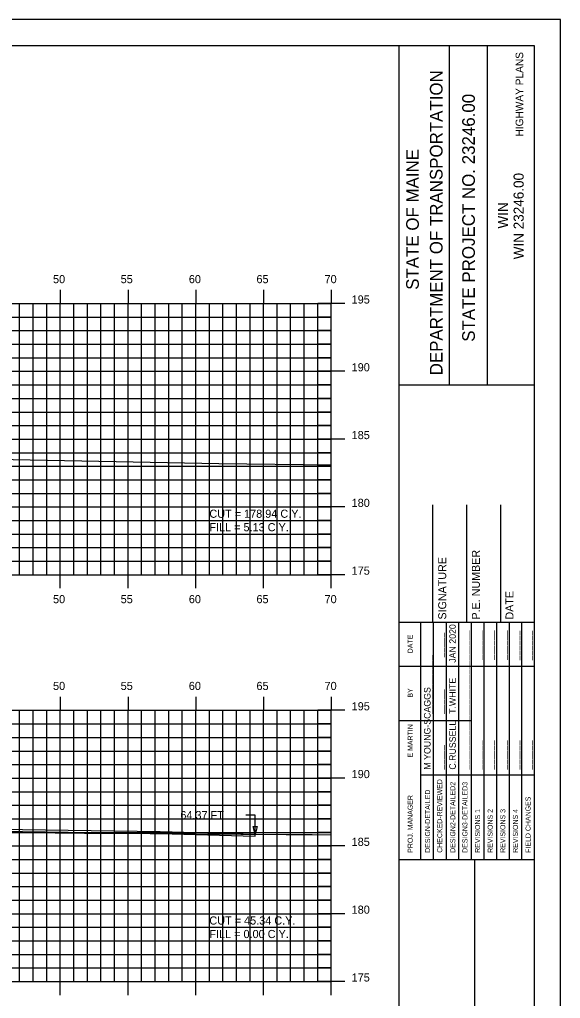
# Model space of a CAD drawing. Extents: x 1139650 to 1139820, y 608981 to 609091.
# Drawn here: x 1139780.2 to 1139820.1, y 609019.1 to 609091.3 of the extents above; entities that cross this region are included whole.
import ezdxf

# ---------------------------------------------------------------- set-up
doc = ezdxf.new("R2010")
doc.units = 0
for name, color, linetype in [('BORDER', 7, 'Continuous'), ('D_Roadway_Edge_Shoulder', 7, 'Continuous'), ('D_Text_Standard', 7, 'Continuous'), ('H_V ANNOTATION', 7, 'Continuous'), ('HIGHWAY_TITLE', 7, 'Continuous'), ('MAJOR', 7, 'Continuous'), ('MINOR', 7, 'Continuous'), ('PLOT BOUNDARY', 7, 'Continuous'), ('S_Roadway_Centerline', 7, 'Continuous')]:
    doc.layers.add(name, color=color, linetype=linetype)

msp = doc.modelspace()

# ---------------------------------------------------------------- linework, layer by layer
at = {"layer": 'BORDER'}
for p, q in [((1139808.219, 608984.335), (1139808.219, 609089.335)), ((1139811.947, 609064.332), (1139811.947, 609089.332)), ((1139814.742, 609064.332), (1139814.742, 609089.332)), ((1139808.219, 609064.329), (1139818.219, 609064.329)), ((1139810.719, 609046.838), (1139810.719, 609055.485)), ((1139813.219, 609046.838), (1139813.219, 609055.485)), ((1139815.719, 609046.838), (1139815.719, 609055.485)), ((1139808.219, 609046.838), (1139818.219, 609046.838)), ((1139808.219, 609029.338), (1139818.219, 609029.338)), ((1139813.81, 608994.338), (1139813.81, 609029.338))]:
    msp.add_line(p, q, dxfattribs=at)
msp.add_lwpolyline([(1139658.219, 608984.335), (1139818.219, 608984.335), (1139818.219, 609089.335), (1139658.219, 609089.335)], close=True, dxfattribs=at)
for points in [[(1139809.833, 609043.588), (1139809.833, 609046.838)], [(1139810.766, 609029.341), (1139810.766, 609046.838)], [(1139811.698, 609046.838), (1139811.698, 609029.341)], [(1139812.629, 609029.341), (1139812.629, 609046.838)], [(1139813.561, 609029.341), (1139813.561, 609046.838)], [(1139814.493, 609029.341), (1139814.493, 609046.838)], [(1139815.424, 609029.341), (1139815.424, 609046.838)], [(1139816.356, 609029.341), (1139816.356, 609046.838)], [(1139817.288, 609029.341), (1139817.288, 609046.838)], [(1139809.834, 609029.341), (1139809.834, 609046.132)], [(1139808.219, 609043.588), (1139818.219, 609043.588)], [(1139808.219, 609039.588), (1139809.834, 609039.588)], [(1139809.833, 609039.588), (1139813.56, 609039.588)], [(1139809.833, 609035.588), (1139818.219, 609035.588)]]:
    msp.add_lwpolyline(points, dxfattribs=at)
at = {"layer": 'D_Roadway_Edge_Shoulder'}
for points in [[(1139797.588, 609031.189), (1139790.588, 609031.365), (1139748.218, 609031.989)], [(1139748.218, 609031.989), (1139748.218, 609031.864), (1139790.588, 609031.24), (1139797.588, 609031.064), (1139797.588, 609031.189)]]:
    msp.add_lwpolyline(points, dxfattribs=at)
at = {"layer": 'D_Text_Standard'}
msp.add_lwpolyline([(1139797.588, 609031.189), (1139797.592, 609032.608), (1139796.913, 609032.608)], dxfattribs=at)
msp.add_lwpolyline([(1139797.588, 609031.189), (1139797.445, 609031.771), (1139797.736, 609031.77)], close=True, dxfattribs=at)
at = {"layer": 'MAJOR'}
for p, q in [((1139783.218, 609071.337), (1139783.218, 609070.335)), ((1139788.218, 609071.337), (1139788.218, 609070.335)), ((1139793.218, 609071.337), (1139793.218, 609070.335)), ((1139798.218, 609071.337), (1139798.218, 609070.335)), ((1139803.218, 609071.337), (1139803.218, 609070.335)), ((1139663.218, 609070.335), (1139803.218, 609070.335)), ((1139663.218, 609070.335), (1139803.218, 609070.335)), ((1139783.218, 609050.335), (1139783.218, 609070.335)), ((1139788.218, 609050.335), (1139788.218, 609070.335)), ((1139793.218, 609050.335), (1139793.218, 609070.335)), ((1139798.218, 609050.335), (1139798.218, 609070.335)), ((1139804.22, 609070.335), (1139802.216, 609070.335)), ((1139803.218, 609050.335), (1139803.218, 609070.335)), ((1139803.218, 609050.335), (1139803.218, 609070.335)), ((1139663.218, 609065.335), (1139803.218, 609065.335)), ((1139804.22, 609065.335), (1139802.216, 609065.335)), ((1139663.218, 609060.335), (1139803.218, 609060.335)), ((1139804.22, 609060.335), (1139802.216, 609060.335)), ((1139663.218, 609055.335), (1139803.218, 609055.335)), ((1139804.22, 609055.335), (1139802.216, 609055.335)), ((1139663.218, 609050.335), (1139803.218, 609050.335)), ((1139663.218, 609050.335), (1139803.218, 609050.335)), ((1139783.218, 609049.333), (1139783.218, 609050.335)), ((1139788.218, 609049.333), (1139788.218, 609050.335)), ((1139793.218, 609049.333), (1139793.218, 609050.335)), ((1139798.218, 609049.333), (1139798.218, 609050.335)), ((1139804.22, 609050.335), (1139802.216, 609050.335)), ((1139803.218, 609049.333), (1139803.218, 609050.335)), ((1139783.218, 609041.337), (1139783.218, 609040.335)), ((1139788.218, 609041.337), (1139788.218, 609040.335)), ((1139793.218, 609041.337), (1139793.218, 609040.335)), ((1139798.218, 609041.337), (1139798.218, 609040.335)), ((1139803.218, 609041.337), (1139803.218, 609040.335)), ((1139663.218, 609040.335), (1139803.218, 609040.335)), ((1139663.218, 609040.335), (1139803.218, 609040.335)), ((1139783.218, 609020.335), (1139783.218, 609040.335)), ((1139788.218, 609020.335), (1139788.218, 609040.335)), ((1139793.218, 609020.335), (1139793.218, 609040.335)), ((1139798.218, 609020.335), (1139798.218, 609040.335)), ((1139804.22, 609040.335), (1139802.216, 609040.335)), ((1139803.218, 609020.335), (1139803.218, 609040.335)), ((1139803.218, 609020.335), (1139803.218, 609040.335)), ((1139663.218, 609035.335), (1139803.218, 609035.335)), ((1139804.22, 609035.335), (1139802.216, 609035.335)), ((1139663.218, 609030.335), (1139803.218, 609030.335)), ((1139804.22, 609030.335), (1139802.216, 609030.335)), ((1139663.218, 609025.335), (1139803.218, 609025.335)), ((1139804.22, 609025.335), (1139802.216, 609025.335)), ((1139663.218, 609020.335), (1139803.218, 609020.335)), ((1139663.218, 609020.335), (1139803.218, 609020.335)), ((1139783.218, 609019.333), (1139783.218, 609020.335)), ((1139788.218, 609019.333), (1139788.218, 609020.335)), ((1139793.218, 609019.333), (1139793.218, 609020.335)), ((1139798.218, 609019.333), (1139798.218, 609020.335)), ((1139804.22, 609020.335), (1139802.216, 609020.335)), ((1139803.218, 609019.333), (1139803.218, 609020.335))]:
    msp.add_line(p, q, dxfattribs=at)
at = {"layer": 'MINOR'}
for p, q in [((1139780.218, 609050.335), (1139780.218, 609070.335)), ((1139781.218, 609050.335), (1139781.218, 609070.335)), ((1139782.218, 609050.335), (1139782.218, 609070.335)), ((1139784.218, 609050.335), (1139784.218, 609070.335)), ((1139785.218, 609050.335), (1139785.218, 609070.335)), ((1139786.218, 609050.335), (1139786.218, 609070.335)), ((1139787.218, 609050.335), (1139787.218, 609070.335)), ((1139789.218, 609050.335), (1139789.218, 609070.335)), ((1139790.218, 609050.335), (1139790.218, 609070.335)), ((1139791.218, 609050.335), (1139791.218, 609070.335)), ((1139792.218, 609050.335), (1139792.218, 609070.335)), ((1139794.218, 609050.335), (1139794.218, 609070.335)), ((1139795.218, 609050.335), (1139795.218, 609070.335)), ((1139796.218, 609050.335), (1139796.218, 609070.335)), ((1139797.218, 609050.335), (1139797.218, 609070.335)), ((1139799.218, 609050.335), (1139799.218, 609070.335)), ((1139800.218, 609050.335), (1139800.218, 609070.335)), ((1139801.218, 609050.335), (1139801.218, 609070.335)), ((1139802.218, 609050.335), (1139802.218, 609070.335)), ((1139663.218, 609069.335), (1139803.218, 609069.335)), ((1139803.218, 609069.335), (1139802.216, 609069.335)), ((1139663.218, 609068.335), (1139803.218, 609068.335)), ((1139803.218, 609068.335), (1139802.216, 609068.335)), ((1139663.218, 609067.335), (1139803.218, 609067.335)), ((1139803.218, 609067.335), (1139802.216, 609067.335)), ((1139663.218, 609066.335), (1139803.218, 609066.335)), ((1139803.218, 609066.335), (1139802.216, 609066.335)), ((1139663.218, 609064.335), (1139803.218, 609064.335)), ((1139803.218, 609064.335), (1139802.216, 609064.335)), ((1139663.218, 609063.335), (1139803.218, 609063.335)), ((1139803.218, 609063.335), (1139802.216, 609063.335)), ((1139663.218, 609062.335), (1139803.218, 609062.335)), ((1139803.218, 609062.335), (1139802.216, 609062.335)), ((1139663.218, 609061.335), (1139803.218, 609061.335)), ((1139803.218, 609061.335), (1139802.216, 609061.335)), ((1139663.218, 609059.335), (1139803.218, 609059.335)), ((1139803.218, 609059.335), (1139802.216, 609059.335)), ((1139663.218, 609058.335), (1139803.218, 609058.335)), ((1139803.218, 609058.335), (1139802.216, 609058.335)), ((1139663.218, 609057.335), (1139803.218, 609057.335)), ((1139803.218, 609057.335), (1139802.216, 609057.335)), ((1139663.218, 609056.335), (1139803.218, 609056.335)), ((1139803.218, 609056.335), (1139802.216, 609056.335)), ((1139663.218, 609054.335), (1139803.218, 609054.335)), ((1139803.218, 609054.335), (1139802.216, 609054.335)), ((1139663.218, 609053.335), (1139803.218, 609053.335)), ((1139803.218, 609053.335), (1139802.216, 609053.335)), ((1139663.218, 609052.335), (1139803.218, 609052.335)), ((1139803.218, 609052.335), (1139802.216, 609052.335)), ((1139663.218, 609051.335), (1139803.218, 609051.335)), ((1139803.218, 609051.335), (1139802.216, 609051.335)), ((1139780.218, 609020.335), (1139780.218, 609040.335)), ((1139781.218, 609020.335), (1139781.218, 609040.335)), ((1139782.218, 609020.335), (1139782.218, 609040.335)), ((1139784.218, 609020.335), (1139784.218, 609040.335)), ((1139785.218, 609020.335), (1139785.218, 609040.335)), ((1139786.218, 609020.335), (1139786.218, 609040.335)), ((1139787.218, 609020.335), (1139787.218, 609040.335)), ((1139789.218, 609020.335), (1139789.218, 609040.335)), ((1139790.218, 609020.335), (1139790.218, 609040.335)), ((1139791.218, 609020.335), (1139791.218, 609040.335)), ((1139792.218, 609020.335), (1139792.218, 609040.335)), ((1139794.218, 609020.335), (1139794.218, 609040.335)), ((1139795.218, 609020.335), (1139795.218, 609040.335)), ((1139796.218, 609020.335), (1139796.218, 609040.335)), ((1139797.218, 609020.335), (1139797.218, 609040.335)), ((1139799.218, 609020.335), (1139799.218, 609040.335)), ((1139800.218, 609020.335), (1139800.218, 609040.335)), ((1139801.218, 609020.335), (1139801.218, 609040.335)), ((1139802.218, 609020.335), (1139802.218, 609040.335)), ((1139663.218, 609039.335), (1139803.218, 609039.335)), ((1139803.218, 609039.335), (1139802.216, 609039.335)), ((1139663.218, 609038.335), (1139803.218, 609038.335)), ((1139803.218, 609038.335), (1139802.216, 609038.335)), ((1139663.218, 609037.335), (1139803.218, 609037.335)), ((1139803.218, 609037.335), (1139802.216, 609037.335)), ((1139663.218, 609036.335), (1139803.218, 609036.335)), ((1139803.218, 609036.335), (1139802.216, 609036.335)), ((1139663.218, 609034.335), (1139803.218, 609034.335)), ((1139803.218, 609034.335), (1139802.216, 609034.335)), ((1139663.218, 609033.335), (1139803.218, 609033.335)), ((1139803.218, 609033.335), (1139802.216, 609033.335)), ((1139663.218, 609032.335), (1139803.218, 609032.335)), ((1139803.218, 609032.335), (1139802.216, 609032.335)), ((1139663.218, 609031.335), (1139803.218, 609031.335)), ((1139803.218, 609031.335), (1139802.216, 609031.335)), ((1139663.218, 609029.335), (1139803.218, 609029.335)), ((1139803.218, 609029.335), (1139802.216, 609029.335)), ((1139663.218, 609028.335), (1139803.218, 609028.335)), ((1139803.218, 609028.335), (1139802.216, 609028.335)), ((1139663.218, 609027.335), (1139803.218, 609027.335)), ((1139803.218, 609027.335), (1139802.216, 609027.335)), ((1139663.218, 609026.335), (1139803.218, 609026.335)), ((1139803.218, 609026.335), (1139802.216, 609026.335)), ((1139663.218, 609024.335), (1139803.218, 609024.335)), ((1139803.218, 609024.335), (1139802.216, 609024.335)), ((1139663.218, 609023.335), (1139803.218, 609023.335)), ((1139803.218, 609023.335), (1139802.216, 609023.335)), ((1139663.218, 609022.335), (1139803.218, 609022.335)), ((1139803.218, 609022.335), (1139802.216, 609022.335)), ((1139663.218, 609021.335), (1139803.218, 609021.335)), ((1139803.218, 609021.335), (1139802.216, 609021.335))]:
    msp.add_line(p, q, dxfattribs=at)
at = {"layer": 'PLOT BOUNDARY'}
msp.add_lwpolyline([(1139650.125, 608981.276), (1139820.125, 608981.276), (1139820.125, 609091.276), (1139650.125, 609091.276)], close=True, dxfattribs=at)
at = {"layer": 'S_Roadway_Centerline'}
for points in [[(1139715.804, 609059.061), (1139723.951, 609060.903), (1139730.764, 609060.998), (1139733.874, 609061.023), (1139735.482, 609060.984), (1139745.746, 609060.665), (1139745.849, 609060.452), (1139745.954, 609060.43), (1139747.1, 609060.358), (1139759.719, 609059.456), (1139769.483, 609059.052), (1139773.402, 609058.957), (1139794.906, 609058.546), (1139803.218, 609058.444)], [(1139779.966, 609031.34), (1139782.848, 609031.308), (1139785.004, 609031.287), (1139789.844, 609031.245), (1139796.548, 609031.195), (1139799.892, 609031.175), (1139801.796, 609031.167), (1139803.218, 609031.164)]]:
    msp.add_lwpolyline(points, dxfattribs=at)

# ---------------------------------------------------------------- texts
at = {"layer": 'BORDER'}
for s, height, p in [('DEPARTMENT OF TRANSPORTATION', 0.93176, (1139811.425, 609065.041)), ('STATE PROJECT NO. 23246.00', 0.93176, (1139813.81, 609067.517)), ('STATE OF MAINE', 0.93176, (1139809.674, 609071.347)), ('WIN 23246.00', 0.74527, (1139817.414, 609073.596)), ('WIN', 0.7453, (1139816.255, 609075.865)), ('SIGNATURE', 0.5906, (1139811.699, 609047.03)), ('P.E. NUMBER', 0.59055, (1139814.179, 609047.03)), ('DATE', 0.5906, (1139816.66, 609047.03)), ('JAN 2020', 0.4845, (1139812.405, 609043.843)), ('DATE', 0.3714, (1139809.223, 609044.544)), ('_____', 0.4845, (1139811.436, 609044.243)), ('______', 0.4845, (1139813.299, 609044.063)), ('______', 0.4845, (1139814.231, 609044.065)), ('______', 0.4845, (1139815.163, 609044.067)), ('______', 0.4845, (1139816.094, 609044.067)), ('______', 0.4845, (1139817.026, 609044.036)), ('______', 0.4845, (1139817.958, 609044.036)), ('____________', 0.48455, (1139810.541, 609040.073)), ('____________', 0.48455, (1139813.299, 609040.073)), ('T.WHITE', 0.4845, (1139812.405, 609040.073)), ('BY', 0.3714, (1139809.223, 609041.273)), ('M YOUNG-SCAGGS', 0.48455, (1139810.541, 609035.961)), ('_____', 0.4845, (1139811.473, 609040.073)), ('____________', 0.48455, (1139813.299, 609035.961)), ('C.RUSSELL', 0.4845, (1139812.405, 609035.961)), ('E MARTIN', 0.3727, (1139809.223, 609036.855)), ('_____', 0.4845, (1139811.436, 609035.961)), ('______', 0.4845, (1139814.231, 609035.961)), ('______', 0.4845, (1139815.163, 609035.961)), ('______', 0.4845, (1139816.094, 609035.961)), ('______', 0.4845, (1139817.026, 609035.961)), ('______', 0.4845, (1139817.958, 609035.961)), ('CHECKED-REVIEWED', 0.37275, (1139811.4, 609029.826)), ('DESIGN2-DETAILED2', 0.37275, (1139812.368, 609029.826)), ('DESIGN3-DETAILED3', 0.37275, (1139813.263, 609029.826)), ('DESIGN-DETAILED', 0.37275, (1139810.505, 609029.826)), ('PROJ. MANAGER', 0.37275, (1139809.223, 609029.826)), ('FIELD CHANGES', 0.37275, (1139817.921, 609029.826)), ('REVISIONS 1', 0.37275, (1139814.195, 609029.826)), ('REVISIONS 2', 0.37275, (1139815.126, 609029.826)), ('REVISIONS 3', 0.37275, (1139816.058, 609029.826)), ('REVISIONS 4', 0.37275, (1139816.99, 609029.826))]:
    msp.add_text(s, height=height, rotation=90, dxfattribs=at).set_placement(p)
at = {"layer": 'D_Text_Standard'}
for s, p in [('CUT = 178.94 C.Y.', (1139794.218, 609054.535)), ('FILL = 5.13 C.Y.', (1139794.218, 609053.539)), ('64.37 FT', (1139792.078, 609032.308)), ('CUT = 45.34 C.Y.', (1139794.218, 609024.535)), ('FILL = 0.00 C.Y.', (1139794.218, 609023.539))]:
    msp.add_text(s, height=0.6, dxfattribs=at).set_placement(p)
at = {"layer": 'H_V ANNOTATION'}
for s, p in [('50', (1139782.683, 609071.835)), ('55', (1139787.675, 609071.835)), ('60', (1139792.704, 609071.835)), ('65', (1139797.696, 609071.835)), ('70', (1139802.72, 609071.835)), ('195', (1139804.718, 609070.335)), ('190', (1139804.718, 609065.335)), ('185', (1139804.718, 609060.335)), ('180', (1139804.718, 609055.335)), ('175', (1139804.718, 609050.335)), ('50', (1139782.683, 609048.235)), ('55', (1139787.675, 609048.235)), ('60', (1139792.704, 609048.235)), ('65', (1139797.696, 609048.235)), ('70', (1139802.72, 609048.235)), ('50', (1139782.683, 609041.835)), ('55', (1139787.675, 609041.835)), ('60', (1139792.704, 609041.835)), ('65', (1139797.696, 609041.835)), ('70', (1139802.72, 609041.835)), ('195', (1139804.718, 609040.335)), ('190', (1139804.718, 609035.335)), ('185', (1139804.718, 609030.335)), ('180', (1139804.718, 609025.335)), ('175', (1139804.718, 609020.335))]:
    msp.add_text(s, height=0.6, dxfattribs=at).set_placement(p)
at = {"layer": 'HIGHWAY_TITLE'}
msp.add_text('HIGHWAY PLANS', height=0.55901, rotation=90, dxfattribs=at).set_placement((1139817.377, 609082.65))

doc.saveas('drawing.dxf')
